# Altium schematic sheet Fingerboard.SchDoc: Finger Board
size Letter; CheckedBy: 1; Author: Jianer Shi; DrawnBy: Jianer Shi; Engineer: Jianer Shi, Borui Chen; Revision: 1
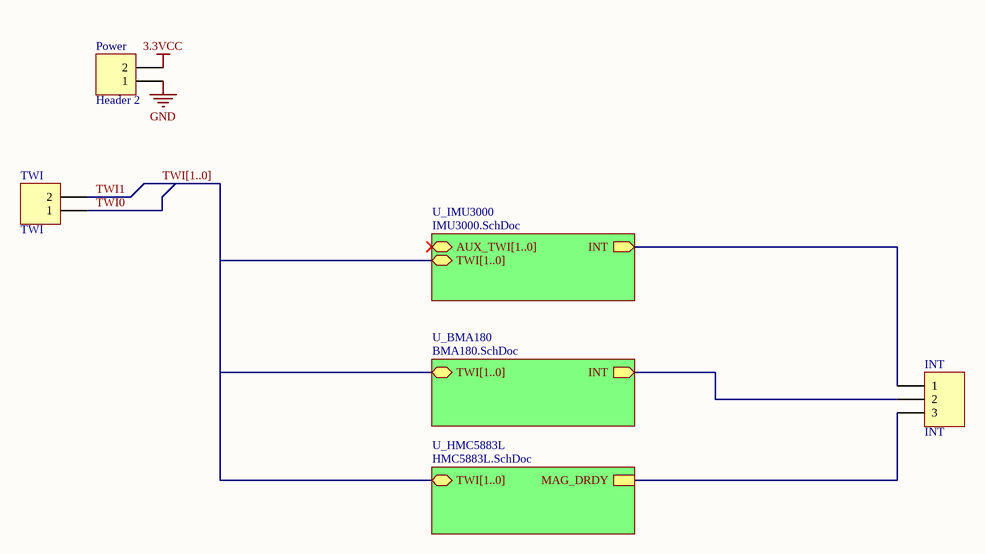
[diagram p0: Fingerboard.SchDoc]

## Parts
INT  INT  [HDR1X3]
Power  Header 2  [HDR1X2]
TWI  TWI  [HDR1X2]

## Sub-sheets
U_BMA180 = BMA180.SchDoc: INT (out), TWI[1..0] (bidir)
U_HMC5883L = HMC5883L.SchDoc: TWI[1..0] (bidir), MAG_DRDY
U_IMU3000 = IMU3000.SchDoc: INT (out), AUX_TWI[1..0] (bidir), TWI[1..0] (bidir)

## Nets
3.3VCC: Power.2
GND: Power.1
TWI0: TWI.1
TWI1: TWI.2
NetINT_1: INT.1 ; sheet U_IMU3000/INT
NetINT_2: INT.2 ; sheet U_BMA180/INT
NetINT_3: INT.3 ; sheet U_HMC5883L/MAG_DRDY

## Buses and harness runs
bus TWI[1..0] = sheet U_BMA180/TWI[1..0] = sheet U_HMC5883L/TWI[1..0] = sheet U_IMU3000/TWI[1..0]

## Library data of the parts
INT = Header 3: Header, 3-Pin
Power TWI = Header 2: Header, 2-Pin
